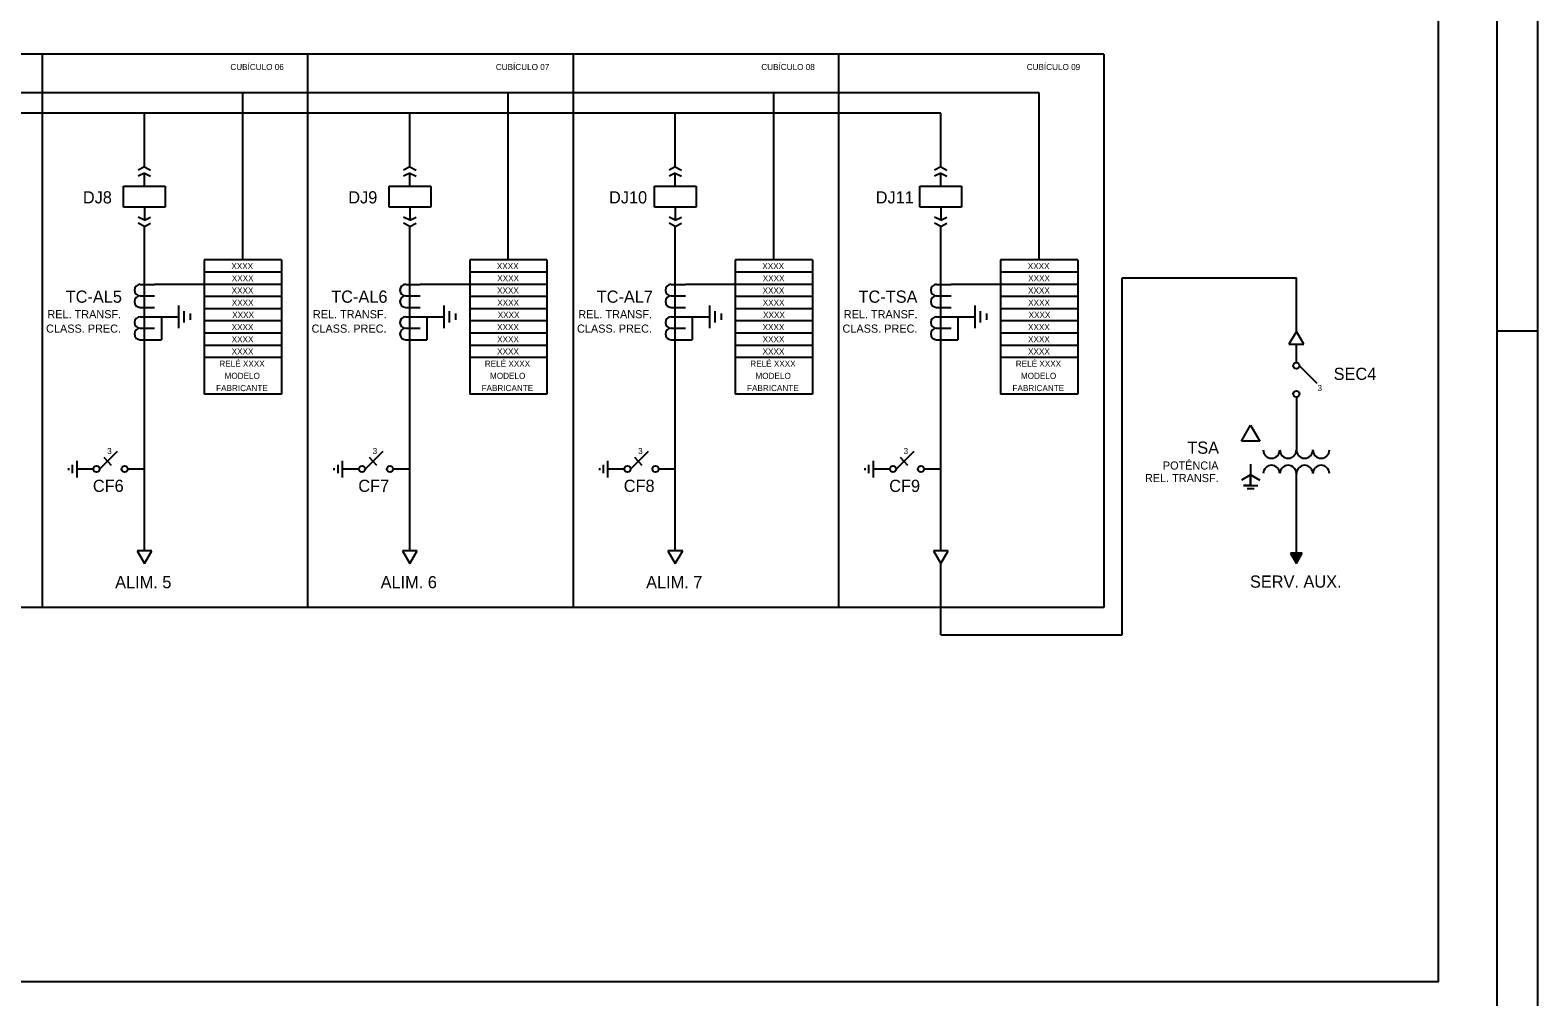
# Model space of a CAD drawing. Extents: x 563 to 1404, y 358 to 952.
# Drawn here: x 1032.8 to 1403.6, y 491.2 to 728.9 of the extents above; entities that cross this region are included whole.
import ezdxf

# ---------------------------------------------------------------- set-up
doc = ezdxf.new("R2010")
doc.units = 0
doc.layers.add('13', color=7, linetype='Continuous')
doc.layers.add('New Level (0)', color=7, linetype='Continuous')

msp = doc.modelspace()

# ---------------------------------------------------------------- linework, layer by layer
for p, q in [((1296.89, 722.95), (622.37, 722.95)), ((1035.78, 722.95), (1035.78, 586.96)), ((1035.78, 722.95), (1035.78, 586.96)), ((1101.05, 722.95), (1101.05, 586.96)), ((1101.05, 722.95), (1101.05, 586.96)), ((1166.33, 722.95), (1166.33, 586.96)), ((1166.33, 722.95), (1166.33, 586.96)), ((1231.61, 722.95), (1231.61, 586.96)), ((1231.61, 722.95), (1231.61, 586.96)), ((1296.89, 722.95), (1296.89, 586.96)), ((1296.89, 722.95), (1296.89, 586.96)), ((1280.96, 713.45), (705.72, 713.45)), ((1085.12, 672.38), (1085.12, 713.45)), ((1150.4, 672.38), (1150.4, 713.45)), ((1215.68, 672.38), (1215.68, 713.45)), ((1280.96, 672.38), (1280.96, 713.45)), ((1256.75, 708.46), (681.52, 708.46)), ((1060.92, 695.25), (1060.92, 708.46)), ((1060.92, 695.25), (1060.92, 708.46)), ((1126.2, 695.25), (1126.2, 708.46)), ((1126.2, 695.25), (1126.2, 708.46)), ((1191.48, 695.25), (1191.48, 708.46)), ((1191.48, 695.25), (1191.48, 708.46)), ((1256.75, 695.25), (1256.75, 708.46)), ((1256.75, 695.25), (1256.75, 708.46)), ((1060.92, 690.5), (1060.92, 693.73)), ((1060.92, 690.5), (1060.92, 693.73)), ((1126.2, 690.5), (1126.2, 693.73)), ((1126.2, 690.5), (1126.2, 693.73)), ((1191.48, 690.5), (1191.48, 693.73)), ((1191.48, 690.5), (1191.48, 693.73)), ((1256.75, 690.5), (1256.75, 693.73)), ((1256.75, 690.5), (1256.75, 693.73)), ((1055.8, 690.5), (1066.04, 690.5)), ((1055.8, 685.38), (1055.8, 690.5)), ((1066.04, 690.5), (1066.04, 685.38)), ((1121.08, 685.38), (1121.08, 690.5)), ((1121.08, 690.5), (1131.32, 690.5)), ((1131.32, 690.5), (1131.32, 685.38)), ((1186.35, 685.38), (1186.35, 690.5)), ((1186.35, 690.5), (1196.6, 690.5)), ((1196.6, 690.5), (1196.6, 685.38)), ((1251.63, 685.38), (1251.63, 690.5)), ((1251.63, 690.5), (1261.87, 690.5)), ((1261.87, 690.5), (1261.87, 685.38)), ((1066.04, 685.38), (1055.8, 685.38)), ((1060.92, 685.38), (1060.92, 682.16)), ((1131.32, 685.38), (1121.08, 685.38)), ((1126.2, 685.38), (1126.2, 682.16)), ((1196.6, 685.38), (1186.35, 685.38)), ((1191.48, 685.38), (1191.48, 682.16)), ((1261.87, 685.38), (1251.63, 685.38)), ((1256.75, 685.38), (1256.75, 682.16)), ((1060.92, 600.87), (1060.92, 680.63)), ((1126.2, 600.87), (1126.2, 680.63)), ((1191.48, 600.87), (1191.48, 680.63)), ((1256.75, 600.87), (1256.75, 680.63)), ((1094.61, 672.38), (1075.63, 672.38)), ((1075.63, 672.38), (1075.63, 639.38)), ((1094.61, 672.38), (1094.61, 639.38)), ((1159.89, 672.38), (1140.91, 672.38)), ((1140.91, 672.38), (1140.91, 639.38)), ((1159.89, 672.38), (1159.89, 639.38)), ((1225.17, 672.38), (1206.19, 672.38)), ((1206.19, 672.38), (1206.19, 639.38)), ((1225.17, 672.38), (1225.17, 639.38)), ((1290.45, 672.38), (1271.46, 672.38)), ((1271.46, 672.38), (1271.46, 639.38)), ((1290.45, 672.38), (1290.45, 639.38)), ((1094.61, 669.38), (1075.63, 669.38)), ((1159.89, 669.38), (1140.91, 669.38)), ((1225.17, 669.38), (1206.19, 669.38)), ((1290.45, 669.38), (1271.46, 669.38)), ((1301.4, 580.16), (1301.4, 667.97)), ((1301.4, 667.97), (1344.19, 667.97)), ((1344.19, 654.77), (1344.19, 667.97)), ((1059.9, 666.38), (1063.43, 666.38)), ((1075.63, 666.38), (1063.43, 666.38)), ((1094.61, 666.38), (1075.63, 666.38)), ((1125.17, 666.38), (1128.71, 666.38)), ((1140.91, 666.38), (1128.71, 666.38)), ((1159.89, 666.38), (1140.91, 666.38)), ((1190.45, 666.38), (1193.99, 666.38)), ((1206.19, 666.38), (1193.99, 666.38)), ((1225.17, 666.38), (1206.19, 666.38)), ((1255.73, 666.38), (1259.27, 666.38)), ((1271.46, 666.38), (1259.27, 666.38)), ((1290.45, 666.38), (1271.46, 666.38)), ((1059.9, 663.55), (1063.43, 663.55)), ((1059.9, 660.72), (1063.43, 660.72)), ((1069.3, 661.21), (1069.3, 655.63)), ((1094.61, 663.38), (1075.63, 663.38)), ((1094.61, 660.38), (1075.63, 660.38)), ((1125.17, 663.55), (1128.71, 663.55)), ((1125.17, 660.72), (1128.71, 660.72)), ((1134.58, 661.21), (1134.58, 655.63)), ((1159.89, 663.38), (1140.91, 663.38)), ((1159.89, 660.38), (1140.91, 660.38)), ((1190.45, 663.55), (1193.99, 663.55)), ((1190.45, 660.72), (1193.99, 660.72)), ((1199.85, 661.21), (1199.85, 655.63)), ((1225.17, 663.38), (1206.19, 663.38)), ((1225.17, 660.38), (1206.19, 660.38)), ((1255.73, 663.55), (1259.27, 663.55)), ((1255.73, 660.72), (1259.27, 660.72)), ((1265.13, 661.21), (1265.13, 655.63)), ((1290.45, 663.38), (1271.46, 663.38)), ((1290.45, 660.38), (1271.46, 660.38)), ((1059.9, 658.42), (1063.43, 658.42)), ((1060.92, 658.42), (1069.3, 658.42)), ((1070.7, 657.02), (1070.7, 659.82)), ((1072.18, 659.2), (1072.18, 657.64)), ((1094.61, 657.38), (1075.63, 657.38)), ((1125.17, 658.42), (1128.71, 658.42)), ((1126.2, 658.42), (1134.58, 658.42)), ((1135.97, 657.02), (1135.97, 659.82)), ((1137.45, 659.2), (1137.45, 657.64)), ((1159.89, 657.38), (1140.91, 657.38)), ((1190.45, 658.42), (1193.99, 658.42)), ((1191.48, 658.42), (1199.85, 658.42)), ((1201.25, 657.02), (1201.25, 659.82)), ((1202.73, 659.2), (1202.73, 657.64)), ((1225.17, 657.38), (1206.19, 657.38)), ((1255.73, 658.42), (1259.27, 658.42)), ((1256.75, 658.42), (1265.13, 658.42)), ((1266.53, 657.02), (1266.53, 659.82)), ((1268.01, 659.2), (1268.01, 657.64)), ((1290.45, 657.38), (1271.46, 657.38)), ((1059.9, 655.59), (1063.43, 655.59)), ((1059.9, 652.76), (1065.11, 652.76)), ((1094.61, 654.38), (1075.63, 654.38)), ((1094.61, 654.38), (1075.63, 654.38)), ((1125.17, 655.59), (1128.71, 655.59)), ((1125.17, 652.76), (1130.39, 652.76)), ((1159.89, 654.38), (1140.91, 654.38)), ((1159.89, 654.38), (1140.91, 654.38)), ((1190.45, 655.59), (1193.99, 655.59)), ((1190.45, 652.76), (1195.66, 652.76)), ((1225.17, 654.38), (1206.19, 654.38)), ((1225.17, 654.38), (1206.19, 654.38)), ((1255.73, 655.59), (1259.27, 655.59)), ((1255.73, 652.76), (1260.94, 652.76)), ((1290.45, 654.38), (1271.46, 654.38)), ((1290.45, 654.38), (1271.46, 654.38)), ((1344.19, 654.77), (1342.38, 651.67)), ((1346, 651.67), (1344.19, 654.77)), ((1094.61, 651.38), (1075.63, 651.38)), ((1159.89, 651.38), (1140.91, 651.38)), ((1225.17, 651.38), (1206.19, 651.38)), ((1290.45, 651.38), (1271.46, 651.38)), ((1342.38, 651.67), (1346, 651.67)), ((1342.38, 651.67), (1346, 651.67)), ((1344.19, 647.12), (1344.19, 651.67)), ((1094.61, 648.38), (1075.63, 648.38)), ((1159.89, 648.38), (1140.91, 648.38)), ((1225.17, 648.38), (1206.19, 648.38)), ((1290.45, 648.38), (1271.46, 648.38)), ((1349.3, 642.02), (1344.96, 646.36)), ((1094.61, 639.38), (1075.63, 639.38)), ((1159.89, 639.38), (1140.91, 639.38)), ((1225.17, 639.38), (1206.19, 639.38)), ((1290.45, 639.38), (1271.46, 639.38)), ((1344.19, 638.68), (1344.19, 625.66)), ((1330.68, 627.86), (1332.94, 631.79)), ((1330.68, 627.86), (1332.94, 631.79)), ((1330.68, 627.86), (1332.94, 631.79)), ((1330.68, 627.86), (1332.94, 631.79)), ((1330.68, 627.86), (1332.94, 631.79)), ((1332.94, 631.79), (1335.2, 627.86)), ((1332.94, 631.79), (1335.2, 627.86)), ((1332.94, 631.79), (1335.2, 627.86)), ((1332.94, 631.79), (1335.2, 627.86)), ((1332.94, 631.79), (1335.2, 627.86)), ((1335.2, 627.86), (1330.68, 627.86)), ((1335.2, 627.86), (1330.68, 627.86)), ((1335.2, 627.86), (1330.68, 627.86)), ((1335.2, 627.86), (1330.68, 627.86)), ((1335.2, 627.86), (1330.68, 627.86)), ((1044.29, 623), (1044.29, 618.91)), ((1054.26, 625.29), (1049.92, 620.95)), ((1050.91, 623.9), (1052.71, 621.88)), ((1109.56, 623), (1109.56, 618.91)), ((1119.54, 625.29), (1115.2, 620.95)), ((1116.19, 623.9), (1117.98, 621.88)), ((1174.84, 623), (1174.84, 618.91)), ((1184.81, 625.29), (1180.47, 620.95)), ((1181.46, 623.9), (1183.26, 621.88)), ((1240.12, 623), (1240.12, 618.91)), ((1250.09, 625.29), (1245.75, 620.95)), ((1246.74, 623.9), (1248.54, 621.88)), ((1042.25, 621.19), (1042.25, 620.66)), ((1043.26, 619.93), (1043.26, 621.98)), ((1048.38, 620.95), (1044.29, 620.95)), ((1060.92, 620.95), (1056.82, 620.95)), ((1107.52, 621.19), (1107.52, 620.66)), ((1108.54, 619.93), (1108.54, 621.98)), ((1113.66, 620.95), (1109.56, 620.95)), ((1126.2, 620.95), (1122.1, 620.95)), ((1172.8, 621.19), (1172.8, 620.66)), ((1173.82, 619.93), (1173.82, 621.98)), ((1178.94, 620.95), (1174.84, 620.95)), ((1191.48, 620.95), (1187.38, 620.95)), ((1238.08, 621.19), (1238.08, 620.66)), ((1239.09, 619.93), (1239.09, 621.98)), ((1244.21, 620.95), (1240.12, 620.95)), ((1256.75, 620.95), (1252.66, 620.95)), ((1332.93, 619.56), (1330.67, 618.26)), ((1332.93, 619.56), (1330.67, 618.26)), ((1332.93, 619.56), (1330.67, 618.26)), ((1332.93, 619.56), (1330.67, 618.26)), ((1332.93, 619.56), (1330.67, 618.26)), ((1332.93, 622.18), (1332.93, 616.95)), ((1332.93, 622.18), (1332.93, 616.95)), ((1332.93, 622.18), (1332.93, 616.95)), ((1332.93, 622.18), (1332.93, 616.95)), ((1332.93, 622.18), (1332.93, 616.95)), ((1332.93, 619.56), (1335.2, 618.26)), ((1332.93, 619.56), (1335.2, 618.26)), ((1335.2, 618.26), (1332.93, 619.56)), ((1332.93, 619.56), (1335.2, 618.26)), ((1335.2, 618.26), (1332.93, 619.56)), ((1332.93, 619.56), (1335.2, 618.26)), ((1335.2, 618.26), (1332.93, 619.56)), ((1332.93, 616.95), (1332.93, 619.56)), ((1332.93, 619.56), (1335.2, 618.26)), ((1335.2, 618.26), (1332.93, 619.56)), ((1344.19, 599.32), (1344.19, 619.85)), ((1331.19, 616.95), (1334.68, 616.95)), ((1332.93, 616.95), (1331.19, 616.95)), ((1331.19, 616.95), (1334.68, 616.95)), ((1332.93, 616.95), (1331.19, 616.95)), ((1331.19, 616.95), (1334.68, 616.95)), ((1332.93, 616.95), (1331.19, 616.95)), ((1331.19, 616.95), (1334.68, 616.95)), ((1332.93, 616.95), (1331.19, 616.95)), ((1333.81, 616.08), (1332.06, 616.08)), ((1333.81, 616.08), (1332.06, 616.08)), ((1333.81, 616.08), (1332.06, 616.08)), ((1333.81, 616.08), (1332.06, 616.08)), ((1333.81, 616.08), (1332.06, 616.08)), ((1332.93, 615.21), (1332.93, 615.21)), ((1332.93, 615.21), (1332.93, 615.21)), ((1332.93, 615.21), (1332.93, 615.21)), ((1332.93, 615.21), (1332.93, 615.21)), ((1332.93, 615.21), (1332.93, 615.21)), ((1062.73, 600.87), (1059.11, 600.87)), ((1062.73, 600.87), (1059.11, 600.87)), ((1059.11, 600.87), (1060.92, 597.77)), ((1060.92, 597.77), (1062.73, 600.87)), ((1124.39, 600.87), (1126.2, 597.77)), ((1128.01, 600.87), (1124.39, 600.87)), ((1128.01, 600.87), (1124.39, 600.87)), ((1126.2, 597.77), (1128.01, 600.87)), ((1193.29, 600.87), (1189.67, 600.87)), ((1189.67, 600.87), (1191.48, 597.77)), ((1193.29, 600.87), (1189.67, 600.87)), ((1191.48, 597.77), (1193.29, 600.87)), ((1258.56, 600.87), (1254.94, 600.87)), ((1254.94, 600.87), (1256.75, 597.77)), ((1258.56, 600.87), (1254.94, 600.87)), ((1256.75, 597.77), (1258.56, 600.87)), ((1256.75, 580.16), (1256.75, 597.77)), ((1345.64, 600.25), (1342.74, 600.25)), ((1342.74, 600.25), (1344.19, 597.77)), ((1342.93, 600.15), (1344.19, 597.98)), ((1345.46, 600.15), (1342.93, 600.15)), ((1345.28, 600.04), (1343.11, 600.04)), ((1343.11, 600.04), (1344.19, 598.18)), ((1345.1, 599.94), (1343.29, 599.94)), ((1343.29, 599.94), (1344.19, 598.39)), ((1343.47, 599.84), (1344.19, 598.6)), ((1344.92, 599.84), (1343.47, 599.84)), ((1343.65, 599.73), (1344.19, 598.8)), ((1344.74, 599.73), (1343.65, 599.73)), ((1344.55, 599.63), (1343.83, 599.63)), ((1343.83, 599.63), (1344.19, 599.01)), ((1344.37, 599.53), (1344.01, 599.53)), ((1344.01, 599.53), (1344.19, 599.22)), ((1344.19, 597.77), (1345.64, 600.25)), ((1344.19, 597.98), (1345.46, 600.15)), ((1344.19, 598.18), (1345.28, 600.04)), ((1344.19, 598.39), (1345.1, 599.94)), ((1344.19, 598.6), (1344.92, 599.84)), ((1344.19, 598.8), (1344.74, 599.73)), ((1344.19, 599.01), (1344.55, 599.63)), ((1344.19, 599.22), (1344.37, 599.53)), ((1296.89, 586.96), (622.37, 586.96)), ((1256.75, 580.16), (1301.4, 580.16))]:
    msp.add_line(p, q)
for centre in [(1344.19, 646.36), (1344.19, 639.45), (1049.15, 620.95), (1056.06, 620.95), (1114.43, 620.95), (1121.33, 620.95), (1179.71, 620.95), (1186.61, 620.95), (1244.98, 620.95), (1251.89, 620.95)]:
    msp.add_circle(centre, 0.768)
for centre, radius, start, end in [((1059.9, 664.97), 1.42, 90, 270), ((1125.17, 664.97), 1.42, 90, 270), ((1190.45, 664.97), 1.42, 90, 270), ((1255.73, 664.97), 1.42, 90, 270), ((1059.9, 662.14), 1.42, 90, 270), ((1125.17, 662.14), 1.42, 90, 270), ((1190.45, 662.14), 1.42, 90, 270), ((1255.73, 662.14), 1.42, 90, 270), ((1059.9, 657.01), 1.42, 90, 270), ((1125.17, 657.01), 1.42, 90, 270), ((1190.45, 657.01), 1.42, 90, 270), ((1255.73, 657.01), 1.42, 90, 270), ((1059.9, 654.18), 1.42, 90, 270), ((1125.17, 654.18), 1.42, 90, 270), ((1190.45, 654.18), 1.42, 90, 270), ((1255.73, 654.18), 1.42, 90, 270), ((1338.09, 625.66), 2.03, 180, 0), ((1342.16, 625.66), 2.03, 180, 0), ((1346.23, 625.66), 2.03, 180, 0), ((1350.29, 625.66), 2.03, 180, 0), ((1338.09, 619.85), 2.03, 0, 180), ((1342.16, 619.85), 2.03, 0, 180), ((1346.23, 619.85), 2.03, 0, 180), ((1350.29, 619.85), 2.03, 0, 180)]:
    msp.add_arc(centre, radius, start, end)
at = {"layer": '13'}
for p, q in [((1060.92, 695.25), (1059.39, 694.49)), ((1060.92, 693.73), (1059.39, 692.97)), ((1060.92, 695.25), (1062.45, 694.49)), ((1060.92, 693.73), (1062.45, 692.97)), ((1126.2, 695.25), (1124.67, 694.49)), ((1126.2, 693.73), (1124.67, 692.97)), ((1126.2, 695.25), (1127.72, 694.49)), ((1126.2, 693.73), (1127.72, 692.97)), ((1191.48, 695.25), (1189.95, 694.49)), ((1191.48, 693.73), (1189.95, 692.97)), ((1191.48, 695.25), (1193, 694.49)), ((1191.48, 693.73), (1193, 692.97)), ((1256.75, 695.25), (1255.23, 694.49)), ((1256.75, 693.73), (1255.23, 692.97)), ((1256.75, 695.25), (1258.28, 694.49)), ((1256.75, 693.73), (1258.28, 692.97)), ((1060.92, 682.16), (1059.39, 682.92)), ((1060.92, 682.16), (1062.45, 682.92)), ((1126.2, 682.16), (1124.67, 682.92)), ((1126.2, 682.16), (1127.72, 682.92)), ((1191.48, 682.16), (1189.95, 682.92)), ((1191.48, 682.16), (1193, 682.92)), ((1256.75, 682.16), (1255.23, 682.92)), ((1256.75, 682.16), (1258.28, 682.92)), ((1060.92, 680.63), (1059.39, 681.4)), ((1060.92, 680.63), (1062.45, 681.4)), ((1126.2, 680.63), (1124.67, 681.4)), ((1126.2, 680.63), (1127.72, 681.4)), ((1191.48, 680.63), (1189.95, 681.4)), ((1191.48, 680.63), (1193, 681.4)), ((1256.75, 680.63), (1255.23, 681.4)), ((1256.75, 680.63), (1258.28, 681.4))]:
    msp.add_line(p, q, dxfattribs=at)
at = {"layer": 'New Level (0)'}
for p, q in [((1403.58, 357.96), (1403.58, 951.96)), ((1403.58, 357.96), (1403.58, 951.96)), ((1393.58, 367.96), (1393.58, 941.96)), ((1393.58, 367.96), (1393.58, 941.96)), ((1065.11, 658.42), (1065.11, 652.76)), ((1130.39, 658.42), (1130.39, 652.76)), ((1195.66, 658.42), (1195.66, 652.76)), ((1260.94, 658.42), (1260.94, 652.76)), ((1393.58, 654.96), (1403.58, 654.96))]:
    msp.add_line(p, q, dxfattribs=at)
msp.add_lwpolyline([(592.61, 760.21), (1379.09, 760.21), (1379.09, 494.89), (592.61, 494.89)], close=True, dxfattribs=at)

# ---------------------------------------------------------------- texts
for s, height, p in [('CUBÍCULO 06', 1.5, (1082.06, 719.09)), ('CUBÍCULO 07', 1.5, (1147.34, 719.09)), ('CUBÍCULO 08', 1.5, (1212.62, 719.09)), ('CUBÍCULO 09', 1.5, (1277.89, 719.09)), ('DJ8', 3, (1045.79, 686.28)), ('DJ9', 3, (1111.06, 686.28)), ('DJ10', 3, (1175.18, 686.28)), ('DJ11', 3, (1240.75, 686.28)), ('XXXX', 1.5, (1082.31, 670.13)), ('XXXX', 1.5, (1147.59, 670.13)), ('XXXX', 1.5, (1212.87, 670.13)), ('XXXX', 1.5, (1278.14, 670.13)), ('XXXX', 1.5, (1082.41, 667.13)), ('XXXX', 1.5, (1147.69, 667.13)), ('XXXX', 1.5, (1212.97, 667.13)), ('XXXX', 1.5, (1278.24, 667.13)), ('TC-AL5', 3, (1041.57, 661.86)), ('XXXX', 1.5, (1082.38, 664.13)), ('TC-AL6', 3, (1106.87, 661.86)), ('XXXX', 1.5, (1147.65, 664.13)), ('TC-AL7', 3, (1172.15, 661.86)), ('XXXX', 1.5, (1212.93, 664.13)), ('TC-TSA', 3, (1236.54, 661.86)), ('XXXX', 1.5, (1278.21, 664.13)), ('REL. TRANSF.', 2, (1037.07, 658.04)), ('XXXX', 1.5, (1082.41, 661.13)), ('REL. TRANSF.', 2, (1102.35, 658.04)), ('XXXX', 1.5, (1147.69, 661.13)), ('REL. TRANSF.', 2, (1167.62, 658.04)), ('XXXX', 1.5, (1212.97, 661.13)), ('REL. TRANSF.', 2, (1232.9, 658.04)), ('XXXX', 1.5, (1278.24, 661.13)), ('CLASS. PREC.', 2, (1036.75, 654.5)), ('XXXX', 1.5, (1082.38, 655.13)), ('XXXX', 1.5, (1082.52, 658.13)), ('CLASS. PREC.', 2, (1102.03, 654.5)), ('XXXX', 1.5, (1147.66, 655.13)), ('XXXX', 1.5, (1147.8, 658.13)), ('CLASS. PREC.', 2, (1167.31, 654.5)), ('XXXX', 1.5, (1212.94, 655.13)), ('XXXX', 1.5, (1213.07, 658.13)), ('CLASS. PREC.', 2, (1232.59, 654.5)), ('XXXX', 1.5, (1278.21, 655.13)), ('XXXX', 1.5, (1278.35, 658.13)), ('XXXX', 1.5, (1082.38, 652.13)), ('XXXX', 1.5, (1147.66, 652.13)), ('XXXX', 1.5, (1212.94, 652.13)), ('XXXX', 1.5, (1278.22, 652.13)), ('XXXX', 1.5, (1082.38, 649.13)), ('XXXX', 1.5, (1147.66, 649.13)), ('XXXX', 1.5, (1212.94, 649.13)), ('XXXX', 1.5, (1278.22, 649.13)), ('RELÉ XXXX', 1.5, (1079.35, 646.13)), ('RELÉ XXXX', 1.5, (1144.63, 646.13)), ('RELÉ XXXX', 1.5, (1209.91, 646.13)), ('RELÉ XXXX', 1.5, (1275.19, 646.13)), ('SEC4', 3, (1353.37, 642.88)), ('FABRICANTE', 1.5, (1078.56, 640.13)), ('MODELO', 1.5, (1080.63, 643.13)), ('FABRICANTE', 1.5, (1143.83, 640.13)), ('MODELO', 1.5, (1145.91, 643.13)), ('FABRICANTE', 1.5, (1209.11, 640.13)), ('MODELO', 1.5, (1211.18, 643.13)), ('FABRICANTE', 1.5, (1274.39, 640.13)), ('MODELO', 1.5, (1276.46, 643.13)), ('3', 1.5, (1349.39, 640.16)), ('TSA', 3, (1317.38, 624.73)), ('3', 1.5, (1051.77, 624.65)), ('3', 1.5, (1117.05, 624.65)), ('3', 1.5, (1182.33, 624.65)), ('3', 1.5, (1247.61, 624.65)), ('POTÊNCIA', 2, (1311.37, 620.83)), ('REL. TRANSF.', 2, (1306.96, 617.76)), ('CF6', 3, (1048.25, 615.34)), ('CF7', 3, (1113.53, 615.34)), ('CF8', 3, (1178.8, 615.34)), ('CF9', 3, (1244.08, 615.34)), ('ALIM. 5', 3, (1053.73, 591.66)), ('ALIM. 6', 3, (1119.02, 591.65)), ('ALIM. 7', 3, (1184.3, 591.64)), ('SERV. AUX.', 3, (1332.79, 591.79))]:
    msp.add_text(s, height=height).set_placement(p)

doc.saveas('drawing.dxf')
